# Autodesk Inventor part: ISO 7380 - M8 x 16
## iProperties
Created: 2006-02
Part Number: ISO 7380 - M8 x 16
Material: Steel, Mild
Description: Hexagon Socket Button Head Screw
Document SubType Name: Modeling
Standard: ISO 7380
Designer: Andy Moles
Standard Revision: Third edition 2004-01-15
Standards Organization: ISO
Language: en-US
Size Designation: M8 x 16
Categories: <MemberInstance><Categories><Category DisplayName="Fasteners" InternalName="e4da775c-781d-43d5-af7c-5136215cf5a6" Mnemonic="FSTN"><Category DisplayName="Bolts"
Density: 1 g/cm^3
Author: Andy Moles
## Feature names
1. Body [Revolution]
2. Slot [Extrusion]
3. Fillet1
4. Chamfer1
